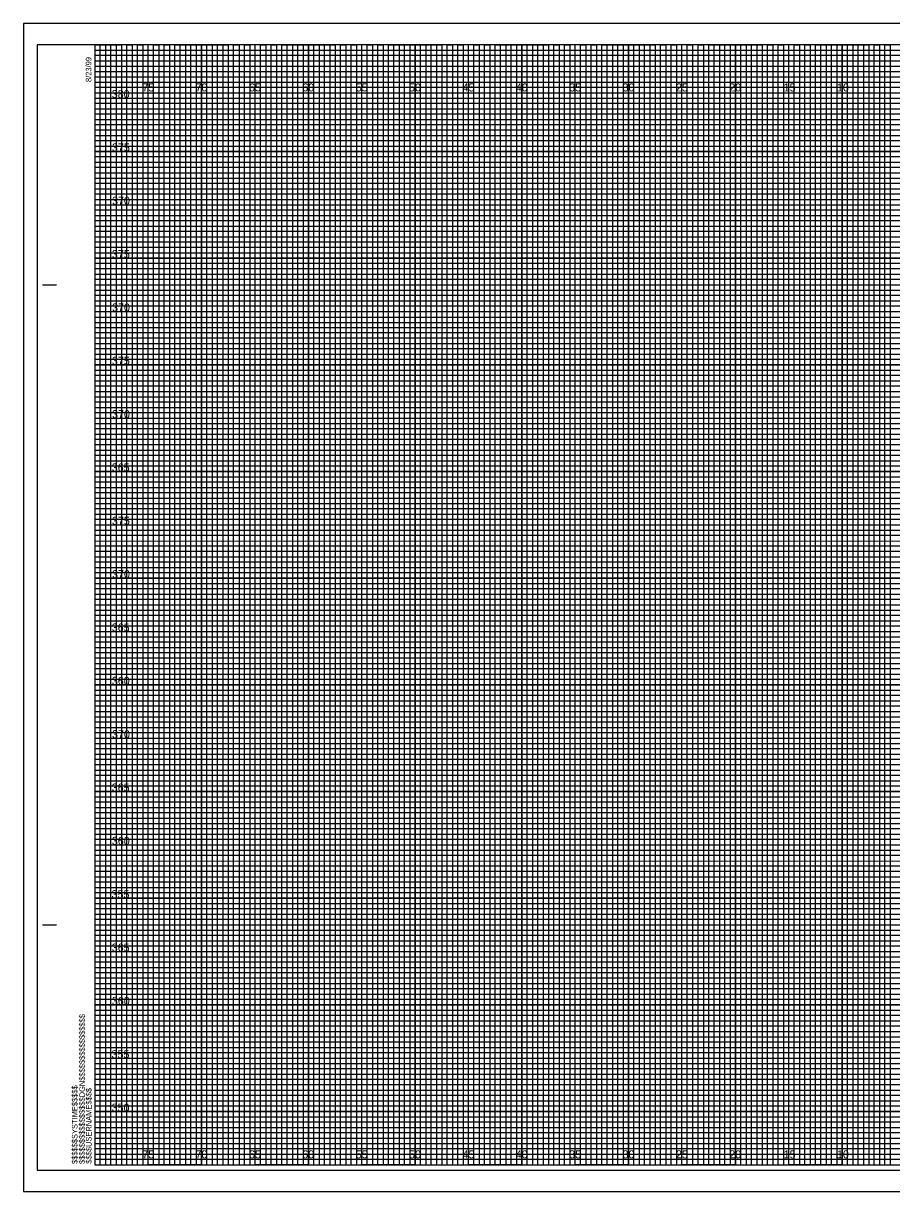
# Model space of a CAD drawing. Extents: x -7 to 162, y 658 to 767.
# Drawn here: x -6.7 to 74.6, y 657.5 to 767 of the extents above; entities that cross this region are included whole.
import ezdxf

# ---------------------------------------------------------------- set-up
doc = ezdxf.new("R2010")
doc.units = 0
for name, color, linetype in [('Prop XS Elevation Labels', 7, 'Continuous'), ('Prop XS Offset Labels', 7, 'Continuous'), ('Sheet Cross Section CELL', 7, 'Continuous'), ('Sheet Cross Section Grid Major CELL', 7, 'Continuous'), ('Sheet Cross Section Grid Middle CELL', 7, 'Continuous'), ('Sheet Cross Section Grid Minor 1 CELL', 7, 'Continuous'), ('Sheet Cross Section Grid Minor 2 CELL', 7, 'Continuous'), ('Sheet Cutting Line CELL', 7, 'Continuous'), ('Sheet DOT Grid CELL', 7, 'Continuous'), ('Sheet Plot Border Inside CELL', 7, 'Continuous'), ('Sheet Plot Border Outside CELL', 7, 'Continuous')]:
    doc.layers.add(name, color=color, linetype=linetype)

msp = doc.modelspace()

# ---------------------------------------------------------------- linework, layer by layer
at = {"layer": 'Sheet Cross Section CELL'}
for p, q in [((-4.9, 742.5), (-3.65, 742.5)), ((-4.85, 742.5), (-3.6, 742.5)), ((-4.9, 682.5), (-3.65, 682.5)), ((-4.85, 682.5), (-3.6, 682.5)), ((0, 660), (0, 660)), ((0, 660), (0, 660)), ((0, 660), (0, 660)), ((0, 660), (0, 660)), ((0, 660), (0, 660)), ((0, 660), (0, 660)), ((0, 660), (0, 660))]:
    msp.add_line(p, q, dxfattribs=at)
msp.add_lwpolyline([(160, 765), (0, 765), (0, 660), (160, 660)], close=True, dxfattribs=at)
at = {"layer": 'Sheet Cross Section Grid Major CELL'}
for p, q in [((5, 765), (0, 765)), ((5, 660), (5, 765)), ((15, 765), (10, 765)), ((10, 765), (10, 660)), ((15, 660), (15, 765)), ((25, 765), (20, 765)), ((20, 765), (20, 660)), ((25, 660), (25, 765)), ((35, 765), (30, 765)), ((30, 765), (30, 660)), ((35, 660), (35, 765)), ((45, 765), (40, 765)), ((40, 765), (40, 660)), ((45, 660), (45, 765)), ((55, 765), (50, 765)), ((50, 765), (50, 660)), ((55, 660), (55, 765)), ((65, 765), (60, 765)), ((60, 765), (60, 660)), ((65, 660), (65, 765)), ((75, 765), (70, 765)), ((70, 765), (70, 660)), ((10, 660), (5, 660)), ((20, 660), (15, 660)), ((30, 660), (25, 660)), ((40, 660), (35, 660)), ((50, 660), (45, 660)), ((60, 660), (55, 660)), ((70, 660), (65, 660))]:
    msp.add_line(p, q, dxfattribs=at)
for points in [[(0, 760), (160, 760), (160, 755), (0, 755)], [(0, 750), (160, 750), (160, 745), (0, 745)], [(0, 740), (160, 740), (160, 735), (0, 735)], [(0, 730), (160, 730), (160, 725), (0, 725)], [(0, 720), (160, 720), (160, 715), (0, 715)], [(0, 710), (160, 710), (160, 705), (0, 705)], [(0, 700), (160, 700), (160, 695), (0, 695)], [(0, 690), (160, 690), (160, 685), (0, 685)], [(0, 680), (160, 680), (160, 675), (0, 675)], [(0, 670), (160, 670), (160, 665), (0, 665)]]:
    msp.add_lwpolyline(points, dxfattribs=at)
at = {"layer": 'Sheet Cross Section Grid Middle CELL'}
for points in [[(0, 765), (2.5, 765), (2.5, 660), (7.5, 660), (7.5, 765), (12.5, 765), (12.5, 660), (17.5, 660), (17.5, 765), (22.5, 765), (22.5, 660), (27.5, 660), (27.5, 765), (32.5, 765), (32.5, 660), (37.5, 660), (37.5, 765), (42.5, 765), (42.5, 660), (47.5, 660), (47.5, 765), (52.5, 765), (52.5, 660), (57.5, 660), (57.5, 765), (62.5, 765), (62.5, 660), (67.5, 660), (67.5, 765), (72.5, 765), (72.5, 660), (77.5, 660)], [(0, 762.5), (137.5, 762.5)], [(0, 752.5), (160, 752.5), (160, 757.5), (0, 757.5)], [(0, 742.5), (160, 742.5), (160, 747.5), (0, 747.5)], [(0, 732.5), (160, 732.5), (160, 737.5), (0, 737.5)], [(0, 722.5), (160, 722.5), (160, 727.5), (0, 727.5)], [(0, 712.5), (160, 712.5), (160, 717.5), (0, 717.5)], [(0, 702.5), (160, 702.5), (160, 707.5), (0, 707.5)], [(0, 692.5), (160, 692.5), (160, 697.5), (0, 697.5)], [(0, 682.5), (160, 682.5), (160, 687.5), (0, 687.5)], [(0, 672.5), (160, 672.5), (160, 677.5), (0, 677.5)], [(0, 662.5), (160, 662.5), (160, 667.5), (0, 667.5)]]:
    msp.add_lwpolyline(points, dxfattribs=at)
at = {"layer": 'Sheet Cross Section Grid Minor 1 CELL'}
for p, q in [((0, 764.5), (130, 764.5)), ((130, 763.99), (0, 763.99)), ((0, 763.99), (0, 763.5)), ((0, 763.5), (130, 763.5)), ((130, 762.95), (0, 762.95)), ((0, 762.95), (0, 762)), ((0, 762), (160, 762))]:
    msp.add_line(p, q, dxfattribs=at)
for points in [[(0, 761.5), (135, 761.5), (160, 761.5), (160, 761), (0, 761)], [(0, 760.5), (160, 760.5), (160, 759.5), (0, 759.5)], [(0, 759), (160, 759), (160, 758.5), (0, 758.49)], [(0, 758), (160, 758), (160, 757), (0, 757)], [(0, 756.5), (160, 756.5), (160, 756), (0, 756)], [(0, 755.5), (160, 755.5), (160, 754.5), (0, 754.5)], [(0, 754), (160, 754), (160, 753.5), (0, 753.5)], [(0, 753), (160, 753), (160, 752), (0, 752)], [(0, 751.5), (160, 751.5), (160, 751), (0, 751)], [(0, 750.5), (160, 750.5), (160, 749.5), (0, 749.5)], [(0, 749), (160, 749), (160, 748.5), (0, 748.5)], [(0, 748), (160, 748), (160, 746.98), (160, 746.5), (160, 746), (0, 746)], [(0, 747), (160, 747), (160, 746.5), (0, 746.5)], [(0, 745.5), (160, 745.5), (160, 744.5), (0, 744.51)], [(0, 744.51), (160, 744.5), (160, 744), (0, 744)], [(0, 743.5), (160, 743.5), (160, 743), (0, 743)], [(0, 742), (160, 742), (160, 741.5), (0, 741.5)], [(0, 741), (160, 741), (160, 740.5), (0, 740.5)], [(-0.04, 739.45), (160, 739.45), (160, 738.94), (-0.04, 738.94)], [(0, 738.5), (160, 738.5), (160, 738), (0, 738)], [(0, 737), (160, 737), (160, 736.5), (0, 736.5)], [(0, 736), (160, 736), (160, 735.5), (0, 735.5)], [(0, 734.5), (160, 734.5), (160, 734), (0, 734)], [(0, 733.5), (160, 733.5), (160, 733), (0, 733)], [(0, 732), (160, 732), (160, 731.5), (0, 731.5)], [(0, 731), (160, 731), (160, 730.5), (0, 730.5)], [(0, 729.5), (160, 729.5), (160, 728.99), (0, 729)], [(0, 728.5), (160, 728.5), (160, 728), (0, 728)], [(0, 727), (160, 727), (160, 726.5), (0, 726.5)], [(0, 726), (160, 726), (160, 725.5), (0, 725.5)], [(0, 724.5), (160, 724.5), (160, 724), (0, 724)], [(0, 723.5), (160, 723.5), (160, 723), (0, 723)], [(0, 722), (160, 722), (160, 721.5), (0, 721.5)], [(0, 721), (160, 721), (160, 720.5), (0, 720.5)], [(0, 719.5), (160, 719.5), (160, 719), (0, 719)], [(0, 718.5), (160.03, 718.46), (160, 718), (0, 718)], [(0, 717), (160, 717), (160, 716.5), (0, 716.5)], [(0, 716), (160, 716), (160, 715.5), (0, 715.5)], [(0, 714.5), (160, 714.5), (160, 714), (0, 714)], [(0, 713.5), (160, 713.5), (160, 713), (0, 713)], [(0, 712), (160, 712), (160, 711.5), (0, 711.5)], [(0, 711), (160, 711), (160, 710.5), (0, 710.5)], [(0, 709.5), (160, 709.5), (160, 709), (0, 709)], [(0, 708.5), (160, 708.5), (160, 708), (0, 708)], [(0, 707), (160, 707), (160, 706.5), (0, 706.5)], [(0, 706), (160, 706), (160, 705.5), (0, 705.5)], [(0, 704.5), (160, 704.5), (160, 704), (0, 704)], [(0, 703.5), (160, 703.5), (160, 703), (0, 703)], [(0, 702), (160, 702), (160, 701.5), (0, 701.5)], [(0, 701), (160, 701), (160, 700.5), (0, 700.5)], [(0, 699.5), (160, 699.5), (160, 698.99), (0, 699)], [(0, 698.5), (160, 698.5), (160, 698), (0, 698)], [(0, 697), (160, 697), (160, 696.5), (0, 696.5)], [(0, 696), (160, 696), (160, 695.5), (0, 695.5)], [(0, 694.5), (160, 694.5), (160, 694), (0, 694)], [(0, 693.5), (160, 693.5), (160, 693), (0, 693)], [(0, 692), (160, 692), (160, 691.5), (0, 691.5)], [(0, 691), (160, 691), (160, 690.5), (0, 690.5)], [(0, 689.5), (160, 689.5), (160, 689), (0, 689)], [(0, 688.5), (160.03, 688.46), (160, 688), (0, 688)], [(0, 687), (160, 687), (160, 686.5), (0, 686.5)], [(0, 686), (160, 686), (160, 685.5), (0, 685.5)], [(0, 684.5), (160, 684.5), (160, 684), (0, 684)], [(0, 683.5), (160, 683.5), (160, 683), (0, 683)], [(0, 682), (160, 682), (160, 681.5), (0, 681.5)], [(0, 681), (160, 681), (160, 680.5), (0, 680.5)], [(0, 679.5), (160, 679.5), (160, 679), (0, 679)], [(0, 678.5), (160, 678.5), (160, 678), (0, 678)], [(0, 677), (160, 677), (160, 676.5), (0, 676.5)], [(0, 676), (160, 676), (160, 675.5), (0, 675.5)], [(0, 674.5), (160, 674.5), (160, 674), (0, 674)], [(0, 673.5), (160, 673.5), (160, 673), (0, 673)], [(0, 672), (160, 672), (160, 671.5), (0, 671.5)], [(0, 671), (160, 671), (160, 670.5), (0, 670.5)], [(0, 669.5), (160, 669.5), (160, 669), (0, 669)], [(0, 668.5), (160, 668.5), (160, 668), (0, 668)], [(0, 667), (160, 667), (160, 666.5), (0, 666.5)], [(0, 666), (160, 666), (160, 665.5), (0, 665.5)], [(0, 664.5), (160, 664.5), (160, 664), (0, 664)], [(0, 663.5), (160, 663.5), (160, 663), (0, 663)], [(0, 662), (160, 662), (160, 661.5), (0, 661.5)], [(0, 661), (160, 661), (160, 660.5), (0, 660.5)]]:
    msp.add_lwpolyline(points, dxfattribs=at)
at = {"layer": 'Sheet Cross Section Grid Minor 2 CELL'}
for points in [[(0, 660), (0.5, 660), (0.5, 765), (1, 765), (1, 660)], [(1, 660), (1.5, 660), (1.5, 765), (2, 765), (2, 660)], [(2.5, 660), (3, 660), (3, 765), (3.5, 765), (3.5, 660)], [(3.5, 660), (4, 660), (4, 765), (4.5, 765), (4.5, 660)], [(5, 660), (5.5, 660), (5.5, 765), (6, 765), (6, 660)], [(6, 660), (6.5, 660), (6.5, 765), (7, 765), (7, 660)], [(7.5, 660), (8, 660), (8, 765), (8.5, 765), (8.5, 660)], [(8.5, 660), (9, 660), (9, 765), (9.5, 765), (9.5, 660)], [(10, 660), (10.5, 660), (10.5, 765), (11, 765), (11, 660)], [(11, 660), (11.5, 660), (11.5, 765), (12, 765), (12, 660)], [(12.5, 660), (13, 660), (13, 765), (13.5, 765), (13.5, 660)], [(13.5, 660), (14, 660), (14, 765), (14.5, 765), (14.5, 660)], [(15, 660), (15.5, 660), (15.5, 765), (16, 765), (16, 660)], [(16, 660), (16.5, 660), (16.5, 765), (17, 765), (17, 660)], [(17.5, 660), (18, 660), (18, 765), (18.5, 765), (18.5, 660)], [(18.5, 660), (19, 660), (19, 765), (19.5, 765), (19.5, 660)], [(20, 660), (20.5, 660), (20.5, 765), (21, 765), (21, 660)], [(21, 660), (21.5, 660), (21.5, 765), (22, 765), (22, 660)], [(22.5, 660), (23, 660), (23, 765), (23.5, 765), (23.5, 660)], [(23.5, 660), (24, 660), (24, 765), (24.5, 765), (24.5, 660)], [(25, 660), (25.5, 660), (25.5, 765), (26, 765), (26, 660)], [(26, 660), (26.5, 660), (26.5, 765), (27, 765), (27, 660)], [(27.5, 660), (28, 660), (28, 765), (28.5, 765), (28.5, 660)], [(28.5, 660), (29, 660), (29, 765), (29.5, 765), (29.5, 660)], [(30, 660), (30.5, 660), (30.5, 765), (31, 765), (31, 660)], [(31, 660), (31.5, 660), (31.5, 765), (32, 765), (32, 660)], [(32.5, 660), (33, 660), (33, 765), (33.5, 765), (33.5, 660)], [(33.5, 660), (34, 660), (34, 765), (34.5, 765), (34.5, 660)], [(35, 660), (35.5, 660), (35.5, 765), (36, 765), (36, 660)], [(36, 660), (36.5, 660), (36.5, 765), (37, 765), (37, 660)], [(37.5, 660), (38, 660), (38, 765), (38.5, 765), (38.5, 660)], [(38.5, 660), (39, 660), (39, 765), (39.5, 765), (39.5, 660)], [(40, 660), (40.5, 660), (40.5, 765), (41, 765), (41, 660)], [(41, 660), (41.5, 660), (41.5, 765), (42, 765), (42, 660)], [(42.5, 660), (43, 660), (43, 765), (43.5, 765), (43.5, 660)], [(43.5, 660), (44, 660), (44, 765), (44.5, 765), (44.5, 660)], [(45, 660), (45.5, 660), (45.5, 765), (46, 765), (46, 660)], [(46, 660), (46.5, 660), (46.5, 765), (47, 765), (47, 660)], [(47.5, 660), (48, 660), (48, 765), (48.5, 765), (48.5, 660)], [(48.5, 660), (49, 660), (49, 765), (49.5, 765), (49.5, 660)], [(50, 660), (50.5, 660), (50.5, 765), (51, 765), (51, 660)], [(51, 660), (51.5, 660), (51.5, 765), (52, 765), (52, 660)], [(52.5, 660), (53, 660), (53, 765), (53.5, 765), (53.5, 660)], [(53.5, 660), (54, 660), (54, 765), (54.5, 765), (54.5, 660)], [(55, 660), (55.5, 660), (55.5, 765), (56, 765), (56, 660)], [(56, 660), (56.5, 660), (56.5, 765), (57, 765), (57, 660)], [(57.5, 660), (58, 660), (58, 765), (58.5, 765), (58.5, 660)], [(58.5, 660), (59, 660), (59, 765), (59.5, 765), (59.5, 660)], [(60, 660), (60.5, 660), (60.5, 765), (61, 765), (61, 660)], [(61, 660), (61.5, 660), (61.5, 765), (62, 765), (62, 660)], [(62.5, 660), (63, 660), (63, 765), (63.5, 765), (63.5, 660)], [(63.5, 660), (64, 660), (64, 765), (64.5, 765), (64.5, 660)], [(65, 660), (65.5, 660), (65.5, 765), (66, 765), (66, 660)], [(66, 660), (66.5, 660), (66.5, 765), (67, 765), (67, 660)], [(67.5, 660), (68, 660), (68, 765), (68.5, 765), (68.5, 660)], [(68.5, 660), (69, 660), (69, 765), (69.5, 765), (69.5, 660)], [(70, 660), (70.5, 660), (70.5, 765), (71, 765), (71, 660)], [(71, 660), (71.5, 660), (71.5, 765), (72, 765), (72, 660)], [(72.5, 660), (73, 660), (73, 765), (73.5, 765), (73.5, 660)], [(73.5, 660), (74, 660), (74, 765), (74.5, 765), (74.5, 660)]]:
    msp.add_lwpolyline(points, dxfattribs=at)
at = {"layer": 'Sheet Cutting Line CELL'}
for p, q in [((161.65, 767), (-6.7, 767)), ((-6.7, 767), (-6.7, 657.5)), ((-6.7, 657.5), (161.65, 657.5))]:
    msp.add_line(p, q, dxfattribs=at)
at = {"layer": 'Sheet DOT Grid CELL'}
for p, q in [((5, 660), (5, 765)), ((10, 660), (10, 765)), ((15, 660), (15, 765)), ((20, 660), (20, 765)), ((25, 660), (25, 765)), ((30, 660), (30, 765)), ((35, 660), (35, 765)), ((40, 660), (40, 765)), ((45, 660), (45, 765)), ((50, 660), (50, 765)), ((55, 660), (55, 765)), ((60, 660), (60, 765)), ((65, 660), (65, 765)), ((70, 660), (70, 765)), ((0, 760), (160, 760)), ((0, 755), (160, 755)), ((0, 750), (160, 750)), ((0, 745), (160, 745)), ((0, 740), (160, 740)), ((0, 735), (160, 735)), ((0, 730), (160, 730)), ((0, 725), (160, 725)), ((0, 720), (160, 720)), ((0, 715), (160, 715)), ((0, 710), (160, 710)), ((0, 705), (160, 705)), ((0, 700), (160, 700)), ((0, 695), (160, 695)), ((0, 690), (160, 690)), ((0, 685), (160, 685)), ((0, 680), (160, 680)), ((0, 675), (160, 675)), ((0, 670), (160, 670)), ((0, 665), (160, 665))]:
    msp.add_line(p, q, dxfattribs=at)
at = {"layer": 'Sheet Plot Border Inside CELL'}
msp.add_lwpolyline([(-5.4, 659.5), (161.2, 659.5), (161.2, 765), (-5.4, 765)], close=True, dxfattribs=at)
at = {"layer": 'Sheet Plot Border Outside CELL'}
msp.add_lwpolyline([(-6.7, 657.5), (161.65, 657.5), (161.65, 767), (-6.7, 767)], close=True, dxfattribs=at)

# ---------------------------------------------------------------- texts
at = {"layer": 'Prop XS Elevation Labels'}
for s, p in [('380', (1.58, 760)), ('375', (1.6, 755)), ('370', (1.61, 750)), ('375', (1.6, 745)), ('370', (1.61, 740)), ('375', (1.6, 735)), ('370', (1.61, 730)), ('365', (1.58, 725)), ('375', (1.6, 720)), ('370', (1.61, 715)), ('365', (1.58, 710)), ('360', (1.59, 705)), ('370', (1.61, 700)), ('365', (1.58, 695)), ('360', (1.59, 690)), ('355', (1.56, 685)), ('365', (1.58, 680)), ('360', (1.59, 675)), ('355', (1.56, 670)), ('350', (1.57, 665))]:
    msp.add_text(s, height=0.75, dxfattribs=at).set_placement(p)
at = {"layer": 'Prop XS Offset Labels'}
for s, p in [('75', (4.44, 760.62)), ('70', (9.43, 760.62)), ('65', (14.44, 760.62)), ('60', (19.43, 760.62)), ('55', (24.44, 760.62)), ('50', (29.43, 760.62)), ('45', (34.44, 760.62)), ('40', (39.43, 760.62)), ('35', (44.44, 760.62)), ('30', (49.43, 760.62)), ('25', (54.44, 760.62)), ('20', (59.43, 760.62)), ('15', (64.53, 760.62)), ('10', (69.52, 760.62)), ('70', (9.43, 660.62)), ('65', (14.44, 660.62)), ('60', (19.43, 660.62)), ('50', (29.43, 660.62)), ('40', (39.43, 660.62)), ('35', (44.44, 660.62)), ('30', (49.43, 660.62)), ('25', (54.44, 660.62)), ('20', (59.43, 660.62)), ('10', (69.52, 660.62)), ('75', (4.44, 660.62)), ('55', (24.44, 660.62)), ('45', (34.44, 660.62)), ('15', (64.53, 660.62))]:
    msp.add_text(s, height=0.75, dxfattribs=at).set_placement(p)
at = {"layer": 'Sheet Cross Section CELL'}
for s, p in [('8/23/99', (-0.33, 761.5)), ('$$$$$$$$$$$$$$$$DGN$$$$$$$$$$$$$$$$', (-0.94, 660.09)), ('$$$$$$SYSTIME$$$$$', (-1.63, 660.09)), ('$$$$USERNAME$$$$', (-0.31, 660.12))]:
    msp.add_text(s, height=0.525, rotation=90, dxfattribs=at).set_placement(p)

doc.saveas('drawing.dxf')
